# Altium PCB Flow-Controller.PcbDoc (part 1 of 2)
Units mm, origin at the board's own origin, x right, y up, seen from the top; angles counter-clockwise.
Board outline 85 x 90 mm, 2 copper layers (Top Layer, Bottom Layer), stack 1.571 mm thick; 113 components, 85 nets, 341 pads, 150 vias.
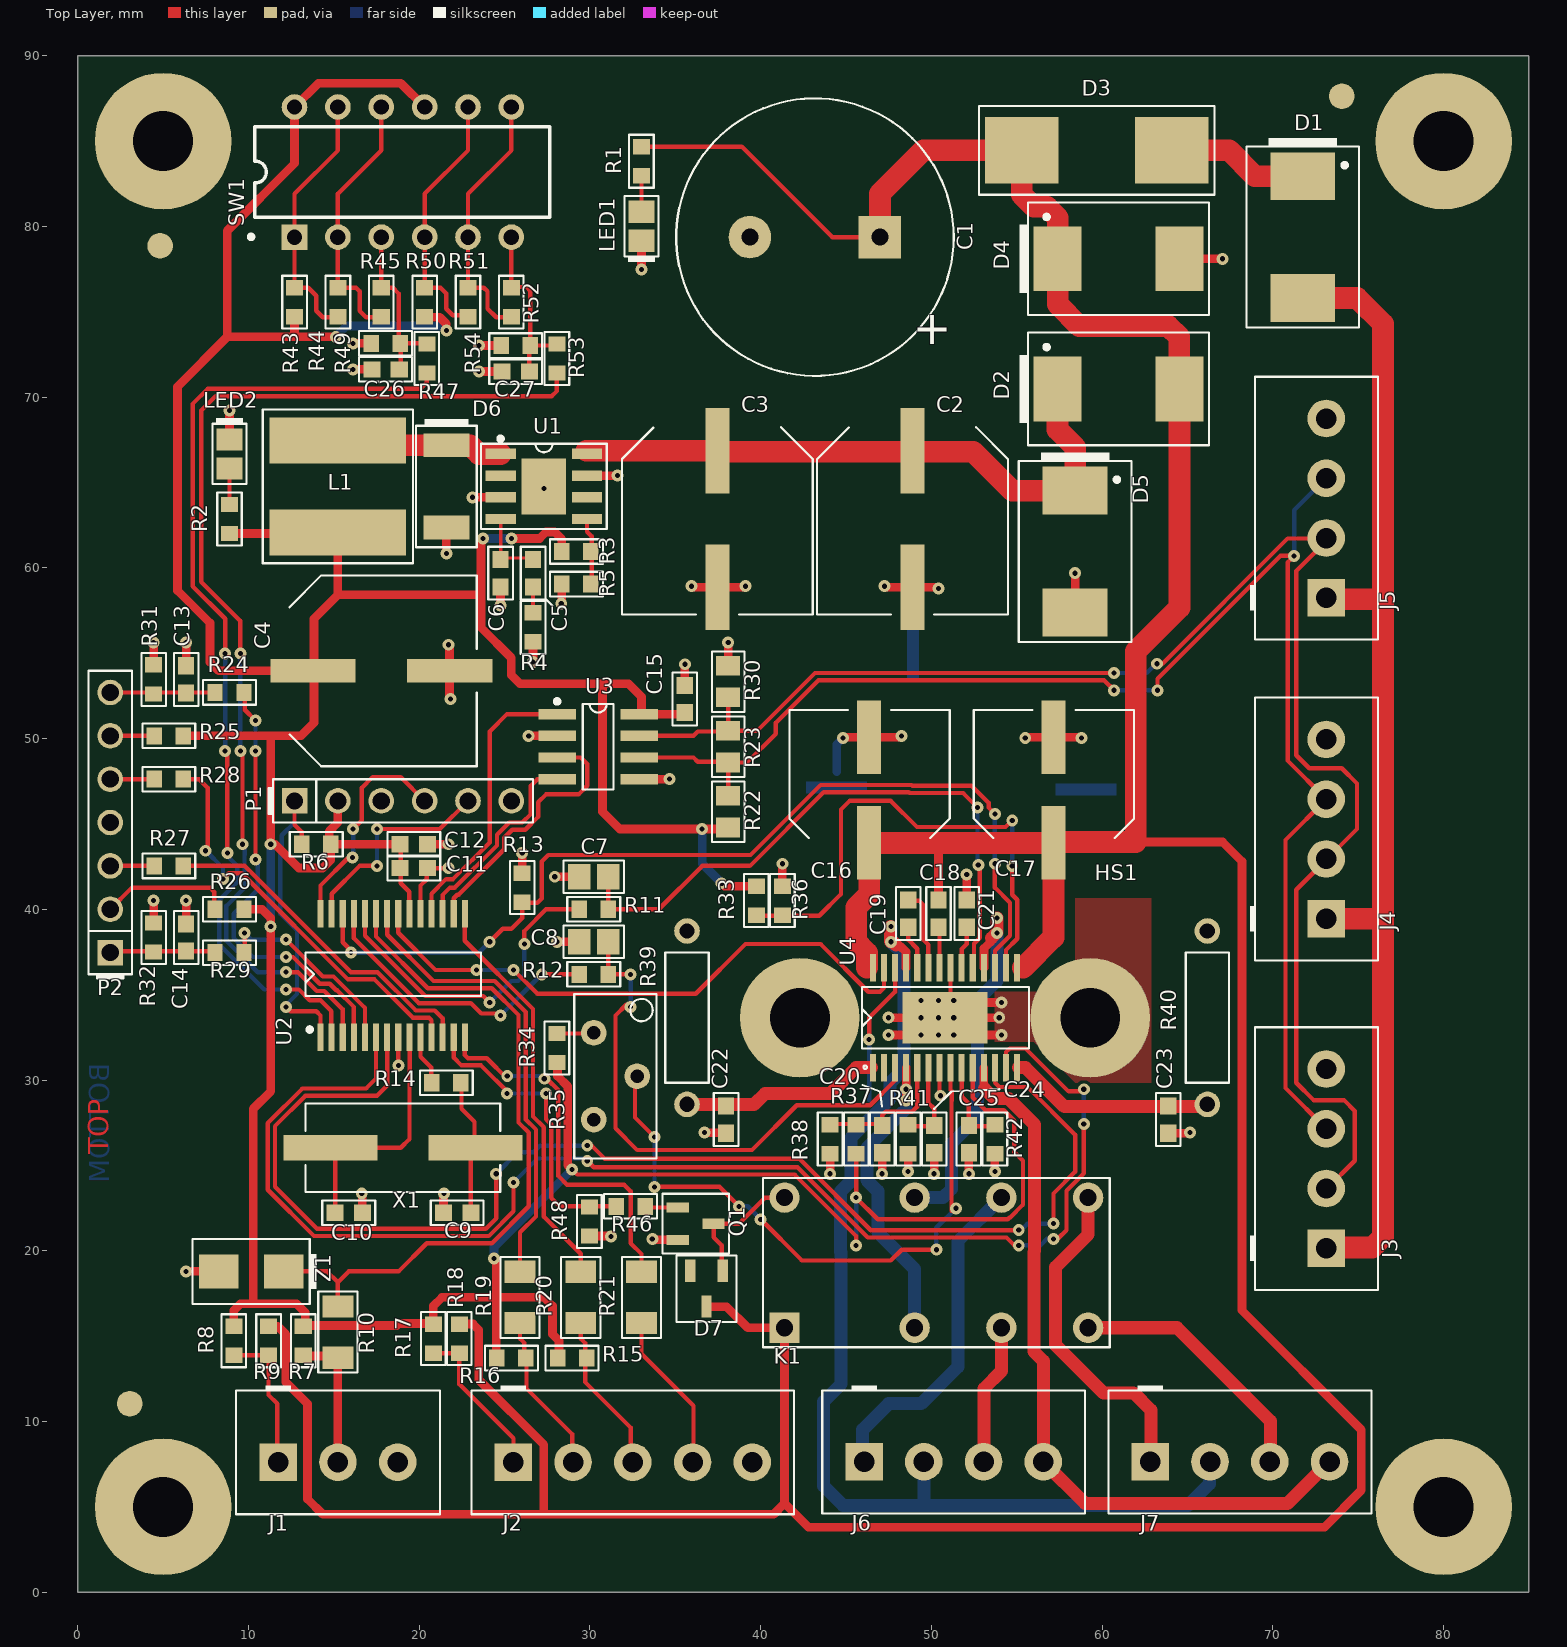
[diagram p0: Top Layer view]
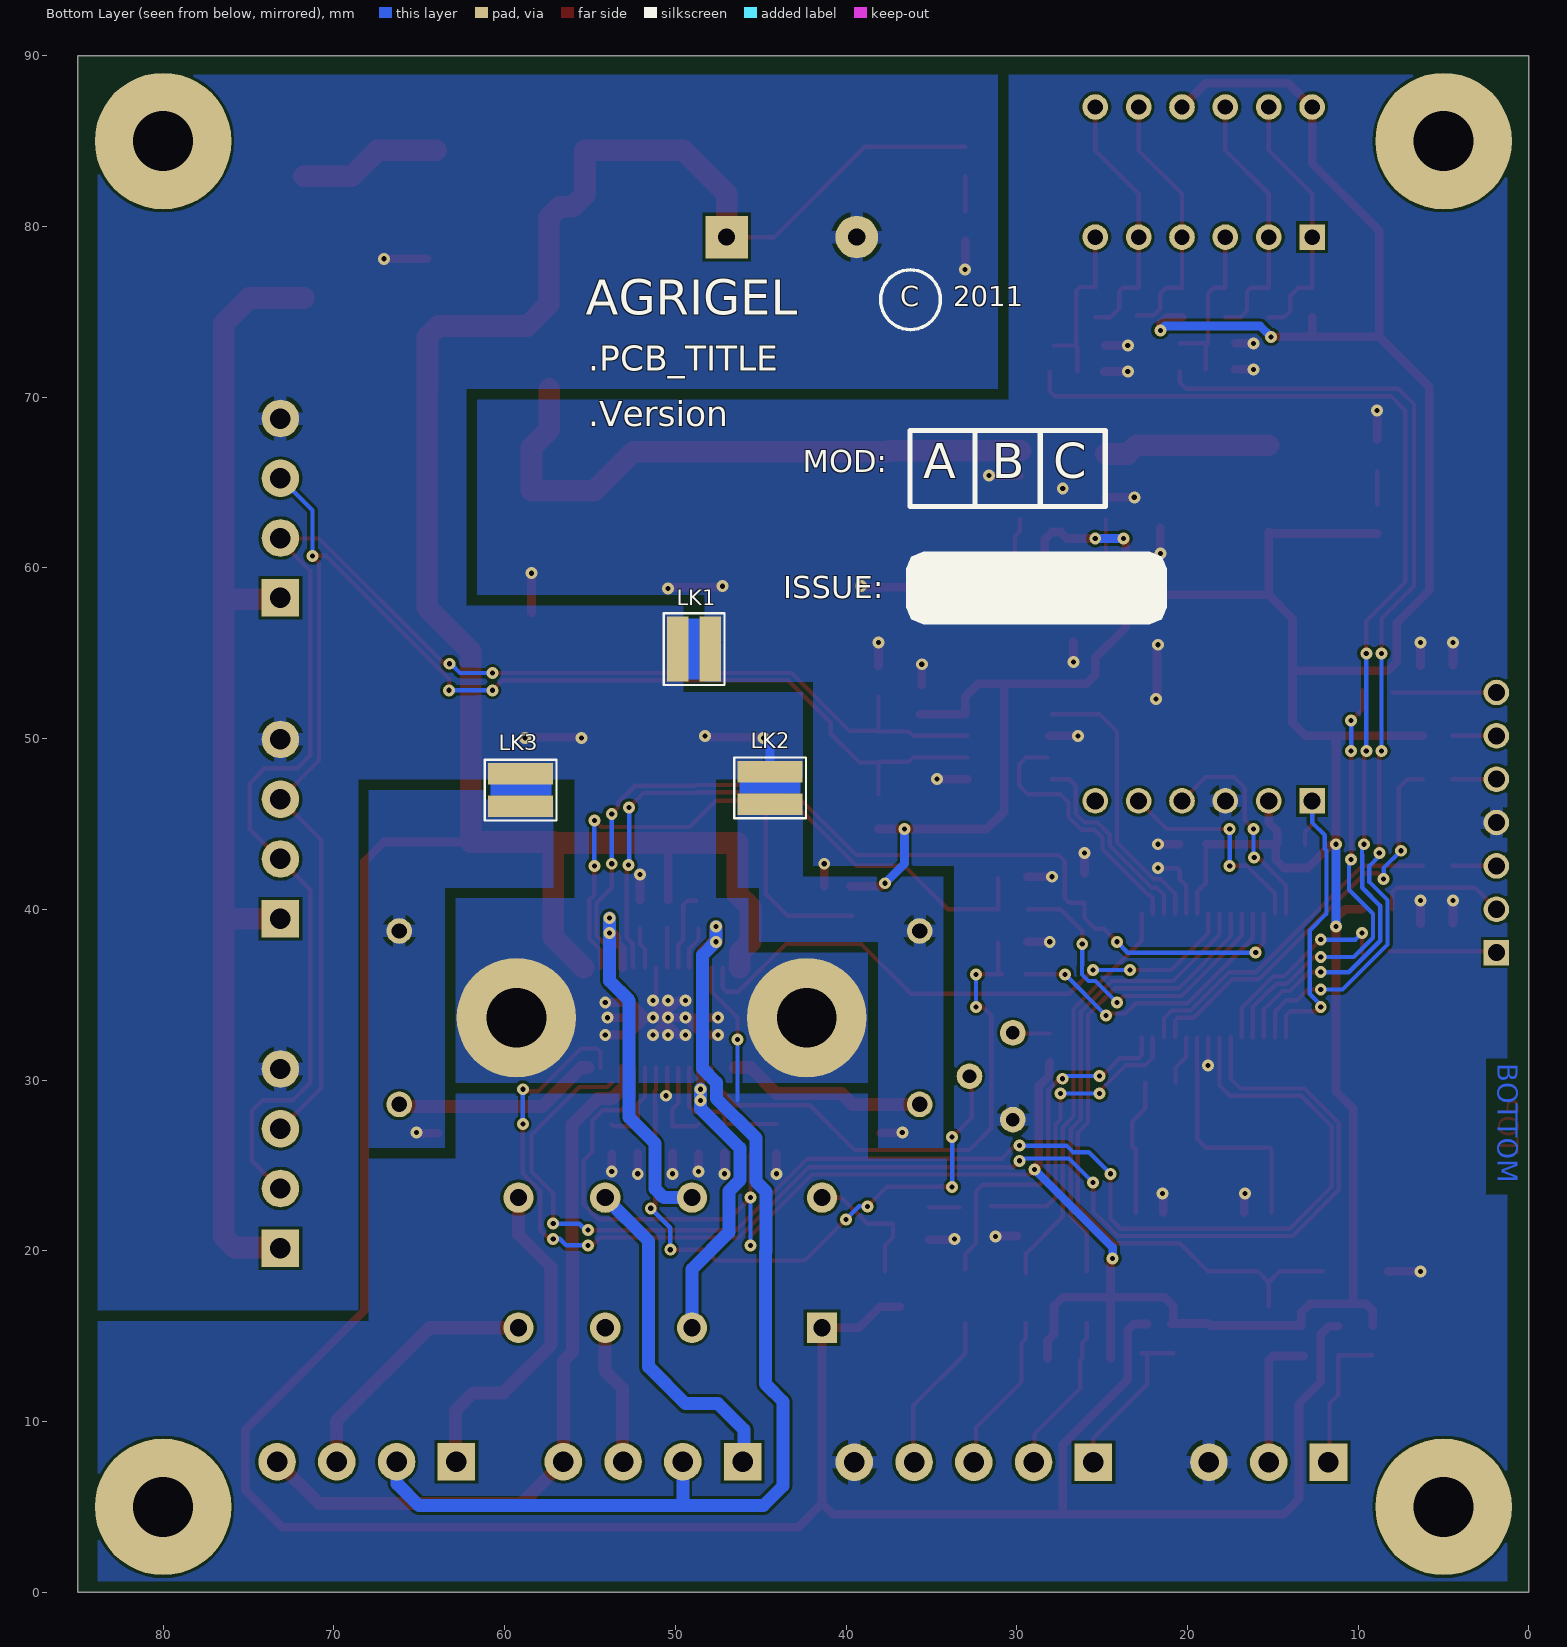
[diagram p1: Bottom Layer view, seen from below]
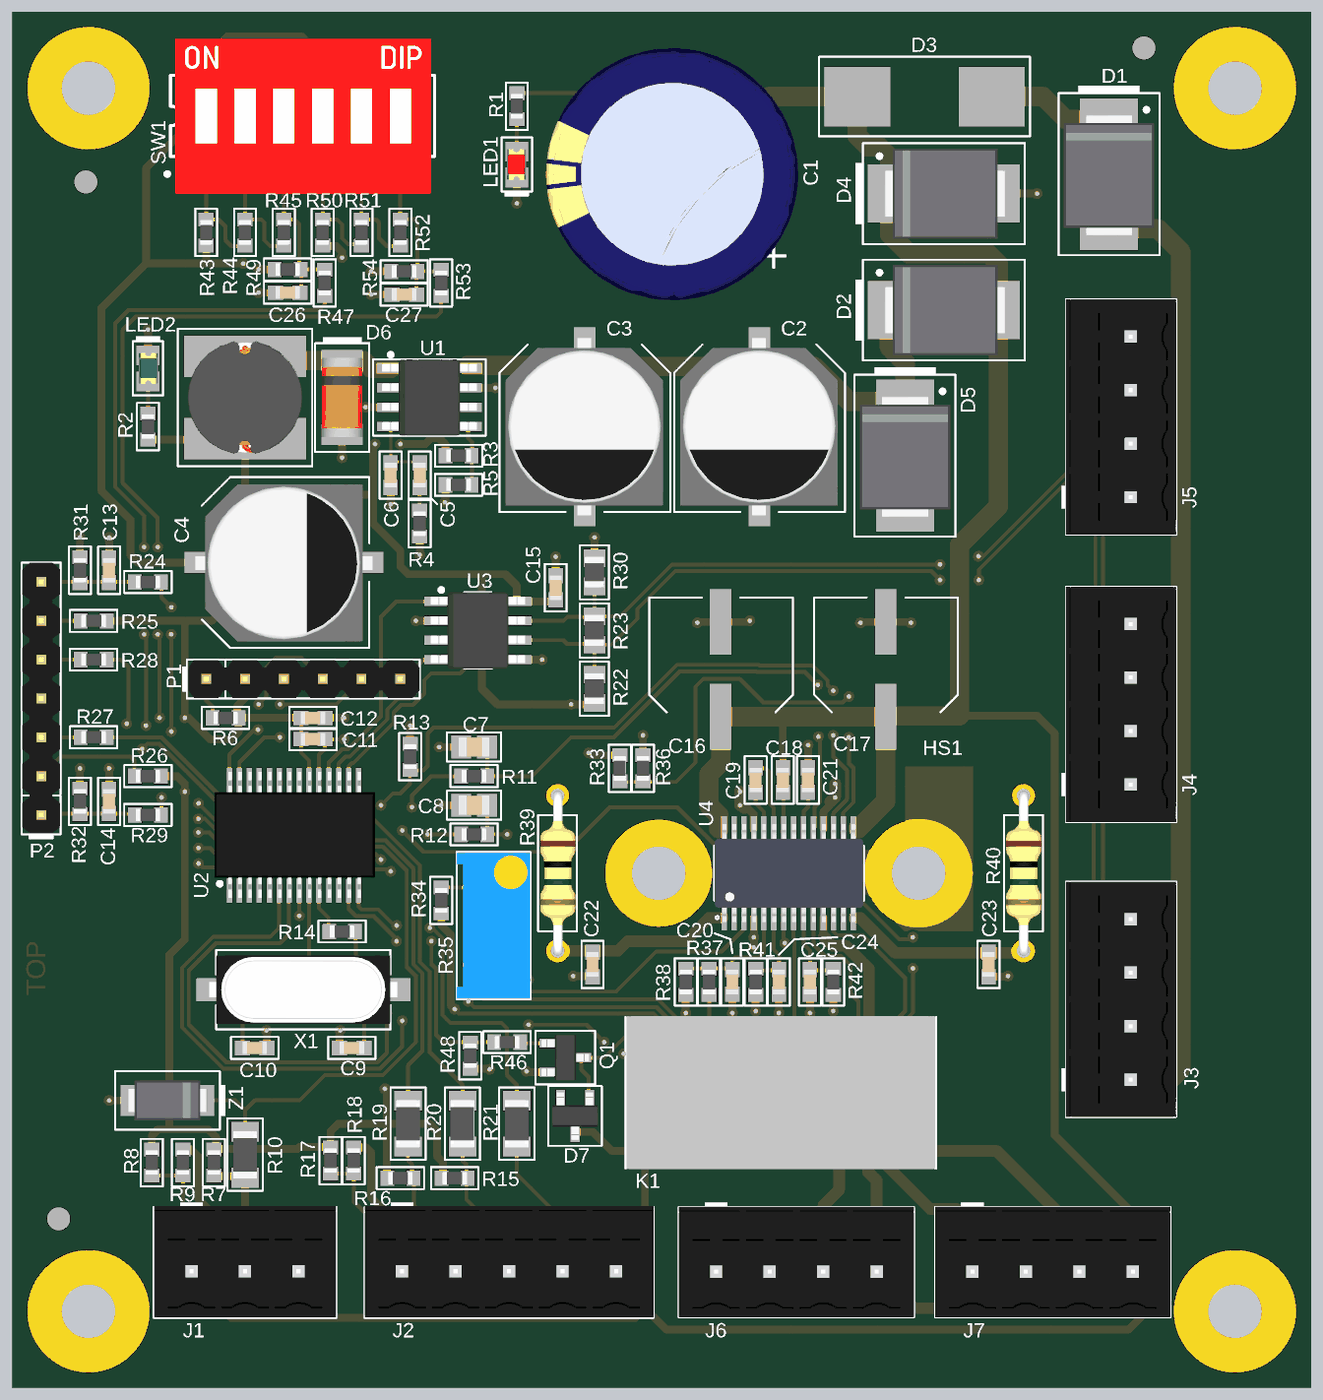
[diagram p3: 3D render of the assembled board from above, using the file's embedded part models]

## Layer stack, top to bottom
Top Layer: signal copper 0.0356
Dielectric: prepreg 1.5, FR-4, Dk 4.2
Bottom Layer: signal copper 0.0356

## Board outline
0,0 85,0 85,90 0,90

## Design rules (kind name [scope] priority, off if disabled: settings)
Clearance [All] p1: gap=0.17
ComponentClearance [All] p1: gap=0 collisioncheckmode=3 verticalgap=0.025 showdistances=FALSE
FabricationTestPointUsage TestPointUsage [All] p1: valid=0 allowmultiple=FALSE
FabricationTestpoint Testpoint [All] p1: side=3 testpointundercomponent=TRUE minsize=1.016 maxsize=2.54 preferedsize=1.524 minholesize=0 maxholesize=1.016 preferedholesize=0.813 testpointgrid=0.025 allowsidetop=TRUE allowsidebottom=TRUE usegrid=TRUE gridtolerance=0
HoleSize [All] p1: absolutevalues=TRUE maxlimit=5 minlimit=0.25 maxpercent=80.000 minpercent=20.000
PlaneClearance [All] p1: clearance=0.5
PolygonConnect PolygonConnect_8 [All vs IsNamedPolygon('Top - GND1-HSK')] p1: connectstyle=Direct reliefconductorwidth=0.254 reliefentries=4 polygonreliefangle="90 Angle" airgapwidth=0.254
PolygonConnect PolygonConnect_7 [All vs IsNamedPolygon('Bot - GND1-HSK')] p2: connectstyle=Direct reliefconductorwidth=0.254 reliefentries=4 polygonreliefangle="90 Angle" airgapwidth=0.254
PolygonConnect PolygonConnect_6 [All vs IsNamedPolygon('Bot - GND4a') Or  IsNamedPolygon('Bot - GND2a') Or  IsNamedPolygon('Bot - GND3a')] p3: connectstyle=Direct reliefconductorwidth=0.254 reliefentries=4 polygonreliefangle="90 Angle" airgapwidth=0.254
PolygonConnect PolygonConnect_5 [All vs IsNamedPolygon('Bot - GND1a')] p4: connectstyle=Direct reliefconductorwidth=0.254 reliefentries=4 polygonreliefangle="90 Angle" airgapwidth=0.254
PolygonConnect PolygonConnectVia [All vs isvia] p5: connectstyle=Direct reliefconductorwidth=0.25 reliefentries=4 polygonreliefangle="90 Angle" airgapwidth=0.254
PolygonConnect PolygonConnect_4 [All vs IsNamedPolygon('Bot - GND2')] p6: connectstyle=Relief reliefconductorwidth=0.762 reliefentries=4 polygonreliefangle="90 Angle" airgapwidth=0.254
PolygonConnect PolygonConnect_3 [All vs IsNamedPolygon('Bot - GND1')] p7: connectstyle=Relief reliefconductorwidth=0.762 reliefentries=4 polygonreliefangle="90 Angle" airgapwidth=0.254
PolygonConnect PolygonConnect_2 [All vs IsNamedPolygon('Bot - GND4')] p8: connectstyle=Relief reliefconductorwidth=0.762 reliefentries=4 polygonreliefangle="90 Angle" airgapwidth=0.254
PolygonConnect PolygonConnect_1 [All vs IsNamedPolygon('Bot - GND3')] p9: connectstyle=Relief reliefconductorwidth=0.762 reliefentries=4 polygonreliefangle="90 Angle" airgapwidth=0.254
PolygonConnect [All] p10: connectstyle=Relief reliefconductorwidth=0.4 reliefentries=4 polygonreliefangle="90 Angle" airgapwidth=0.254
RoutingCorners [All] p1: cornerstyle=45-Degree minsetback=2.5 maxsetback=2.5
RoutingVias [All] p1: holewidth=0.3 width=0.7 viastyle="Through Hole" minholewidth=0.3 minwidth=0.7 maxholewidth=0.3 maxwidth=0.7
ShortCircuit ShortCircuit_LK1 [(InComponent('LK1'))] p1: allowed=TRUE
ShortCircuit ShortCircuit_LK2 [(InComponent('LK2'))] p2: allowed=TRUE
ShortCircuit ShortCircuit_LK3 [(InComponent('LK3'))] p3: allowed=TRUE
ShortCircuit [All] p4: allowed=FALSE
SilkToSolderMaskClearance SilkscreenOverComponentPads [IsPad] p1: minsilkscreentomaskgap=0.254 clearancetoexposedcopper=TRUE
SolderMaskExpansion [All] p1: expansion=0.05
Width "Width_High Power" [InNetClass('High Power')] p1: maxlimit=1.5 minlimit=0.5 preferedwidth=1
Width Width_Power [InNetClass('Power')] p2: maxlimit=1 minlimit=0.3 preferedwidth=0.5
Width [All] p3: maxlimit=2 minlimit=0.2 preferedwidth=0.2
20 further rules are at their usual default settings.

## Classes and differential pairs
component class Flow-Controller-2: C16 C17 C18 C19 C20 C21 C22 C23 C24 C25 C26 C27 D7 HS1 J6 J7 K1 Q1 R33 R34 R35 R36 R37 R38 R39 R40 R41 R42 R43 R44 R45 R46 R47 R48 R49 R50 R51 R52 R53 R54 SW1 U4
component class Flow-Controller-1: C1 C2 C3 C4 C5 C6 C7 C8 C9 C10 C11 C12 C13 C14 C15 D1 D2 D3 D4 D5 D6 J1 J2 J3 J4 J5 L1 LED1 LED2 LK1 LK2 LK3 P1 P2 R1 R2 R3 R4 R5 R6 R7 R8 R9 R10 R11 R12 R13 R14 R15 R16 R17 R18 R19 R20 R21 R22 R23 R24 R25 R26 R27 R28 R29 R30 R31 R32 U1 U2 U3 X1 Z1

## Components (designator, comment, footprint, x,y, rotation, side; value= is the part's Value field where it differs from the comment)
C1 "CAP-EL_2200uF_35V_20%-YXF" EL-RAD-16X31.5 43.18,79.375 r180 top
C2 "100uF35V-20%-EEVFC" CAP-EL-SMD-10x10.5 48.895,62.865 r270 top
C3 "100uF35V-20%-EEVFC" CAP-EL-SMD-10x10.5 37.465,62.865 r270 top
C4 "470uF-35V-20%-LZ" CAP-EL-SMD-10x10.5 17.78,53.975 r0 top
C5 "22nF_C0603_50V_10%_X7R" CAPC0603X85N 26.67,59.69 r270 top
C6 "220pF_C0603_50V_10%_NP0" CAPC0603X85N 24.765,59.69 r270 top
C7 "DNF_C0805_50V_10%_X7R" CAPC0805X110N 30.226,41.91 r180 top
C8 "DNF_C0805_50V_10%_X7R" CAPC0805X110N 30.226,38.1 r180 top
C9 "33pF_C0603_50V_10%_NP0" CAPC0603X85N 22.225,22.225 r180 top
C10 "33pF_C0603_50V_10%_NP0" CAPC0603X85N 15.875,22.225 r0 top
C11 "10nF_C0603_50V_10%_X7R" CAPC0603X85N 19.685,42.418 r0 top
C12 "100nF_C0603_50V_10%_X7R" CAPC0603X85N 19.685,43.815 r0 top
C13 "10nF_C0603_50V_10%_X7R" CAPC0603X85N 6.35,53.467 r90 top
C14 "10nF_C0603_50V_10%_X7R" CAPC0603X85N 6.35,38.354 r90 top
C15 "100nF_C0603_50V_10%_X7R" CAPC0603X85N 35.56,52.324 r90 top
C16 "100uF-50V-20%-LZ" CAP-EL-SMD-8x10.5 46.355,46.99 r90 top
C17 "100uF-50V-20%-LZ" CAP-EL-SMD-8x10.5 57.15,46.99 r90 top
C18 "220nF_C0603_50V_10%_X7R" CAPC0603X85N 50.419,39.751 r270 top
C19 "220nF_C0603_50V_10%_X7R" CAPC0603X85N 48.641,39.751 r90 top
C20 "100nF_C0603_50V_10%_X7R" CAPC0603X85N 47.117,26.543 r270 top
C21 "220nF_C0603_50V_10%_X7R" CAPC0603X85N 52.07,39.751 r90 top
C22 "100nF_C0603_50V_10%_X7R" CAPC0603X85N 37.973,27.686 r270 top
C23 "100nF_C0603_50V_10%_X7R" CAPC0603X85N 63.881,27.686 r270 top
C24 "1.0nF_C0603_50V_10%_X7R" CAPC0603X85N 50.165,26.543 r270 top
C25 "1.0nF_C0603_50V_10%_X7R" CAPC0603X85N 52.197,26.543 r270 top
C26 "100nF_C0603_50V_10%_X7R" CAPC0603X85N 18.034,71.628 r180 top
C27 "100nF_C0603_50V_10%_X7R" CAPC0603X85N 25.654,71.501 r180 top
D1 "ER3M" SMC 71.755,79.375 r270 top
D2 "ER3M" SMC 60.96,70.485 r0 top
D3 "0160 003. MR" LF-0160 59.69,84.455 r180 top
D4 "SMCJ26A" SMC 60.96,78.105 r0 top
D5 "SMCJ26A" SMC 58.42,60.96 r270 top
D6 "SMS2100" DO-213AB 21.59,64.77 r270 top
D7 "BAS16" SOT23 36.83,17.78 r270 top
HS1 "Heatsink-A3979" HEATSINK-A3979 50.8,33.655 r90 top
J1 "MCV 1,5/3-G-3.5" MCV350-3-V 15.24,7.62 r180 top
J2 "MCV 1,5/5-G-3.5" MCV350-5-V 32.512,7.62 r180 top
J3 "MCV 1,5/4-G-3.5" MCV350-4-V 73.152,25.4 r270 top
J4 "MCV 1,5/4-G-3.5" MCV350-4-V 73.152,44.704 r270 top
J5 "MCV 1,5/4-G-3.5" MCV350-4-V 73.152,63.5 r270 top
J6 "MCV 1,5/4-G-3.5" MCV350-4-V 51.308,7.62 r180 top
J7 "MCV 1,5/4-G-3.5" MCV350-4-V 68.072,7.62 r180 top
K1 "V23105-A5003-A201-12V" REL-D2n 50.292,19.304 r90 top
L1 "SDR0805-330K" SDR0805 15.24,64.77 r270 top
LED1 "RED_0805_SMD" LED0805-Red 33.02,80.01 r90 top
LED2 "GREEN_0805_SMD" LED0805-Green 8.89,66.675 r270 top
LK1 "Link-SMD-10A-Closed" SLINK-10A-C 48.895,55.245 r180 bottom
LK2 "Link-SMD-10A-Closed" SLINK-10A-C 44.45,47.117 r270 bottom
LK3 "Link-SMD-10A-Closed" SLINK-10A-C 59.055,46.99 r270 bottom
P1 "SIL6P-2.54" SIL6P-2.54 19.05,46.355 r0 top
P2 "SIL7P-2.54" SIL7P-2.54 1.905,45.085 r90 top
Q1 "BC817" SOT23 36.195,21.59 r0 top
R1 "10K_R0603_1%" RESC0603X60N 33.02,83.82 r270 top
R2 "470R_R0603_1%" RESC0603X60N 8.89,62.865 r90 top
R3 "10K_R0603_1%" RESC0603X60N 29.21,60.96 r0 top
R4 "4K7_R0603_1%" RESC0603X60N 26.67,56.515 r270 top
R5 "3K3_R0603_1%" RESC0603X60N 29.21,59.055 r180 top
R6 "10K_R0603_1%" RESC0603X60N 13.97,43.815 r180 top
R7 "10K_R0603_1%" RESC0603X60N 13.208,14.732 r270 top
R8 "0R_R0603_1%" RESC0603X60N 9.144,14.732 r270 top
R9 "DNP_R0603_1%" RESC0603X60N 11.176,14.732 r270 top
R10 "100R_R1206_1%" RESC1206X71N 15.24,15.24 r270 top
R11 "1K_R0603_1%" RESC0603X60N 30.226,40.005 r0 top
R12 "1K_R0603_1%" RESC0603X60N 30.226,36.195 r0 top
R13 "2K2_R0603_1%" RESC0603X60N 26.035,41.275 r90 top
R14 "0R_R0603_1%" RESC0603X60N 21.59,29.845 r180 top
R15 "1K_R0603_1%" RESC0603X60N 28.956,13.716 r0 top
R16 "10K_R0603_1%" RESC0603X60N 25.4,13.716 r0 top
R17 "0R_R0603_1%" RESC0603X60N 20.828,14.859 r270 top
R18 "DNP_R0603_1%" RESC0603X60N 22.352,14.859 r270 top
R19 "100R_R1206_1%" RESC1206X71N 25.908,17.272 r270 top
R20 "100R_R1206_1%" RESC1206X71N 29.464,17.272 r270 top
R21 "100R_R1206_1%" RESC1206X71N 33.02,17.272 r270 top
R22 "DNP_R0805_1%" RESC0805X65N 38.1,45.72 r90 top
R23 "DNP_R0805_1%" RESC0805X65N 38.1,49.53 r90 top
R24 "1K_R0603_1%" RESC0603X60N 8.89,52.705 r180 top
R25 "1K8_R0603_1%" RESC0603X60N 5.334,50.165 r180 top
R26 "1K_R0603_1%" RESC0603X60N 8.89,40.005 r180 top
R27 "470R_R0603_1%" RESC0603X60N 5.334,42.545 r180 top
R28 "470R_R0603_1%" RESC0603X60N 5.334,47.625 r180 top
R29 "1K_R0603_1%" RESC0603X60N 8.89,37.465 r180 top
R30 "DNP_R0805_1%" RESC0805X65N 38.1,53.34 r90 top
R31 "1K_R0603_1%" RESC0603X60N 4.445,53.467 r90 top
R32 "1K_R0603_1%" RESC0603X60N 4.445,38.354 r90 top
R33 "DNP_R0603_1%" RESC0603X60N 39.751,40.513 r270 top
R34 "2K2_R0603_1%" RESC0603X60N 28.067,31.877 r90 top
R35 "3296Y-1-103" 3296Y-THP 31.496,30.226 r270 top
R36 "1K_R0603_1%" RESC0603X60N 41.275,40.513 r90 top
R37 "4K7_R0603_1%" RESC0603X60N 45.593,26.543 r90 top
R38 "4K7_R0603_1%" RESC0603X60N 44.069,26.543 r270 top
R39 "0R27-0.250W-5%" RES-0.250W 35.687,33.655 r270 top
R40 "0R27-0.250W-5%" RES-0.250W 66.167,33.655 r270 top
R41 "33K_R0603_1%" RESC0603X60N 48.641,26.543 r270 top
R42 "33K_R0603_1%" RESC0603X60N 53.721,26.543 r270 top
R43 "3K9_R0603_1%" RESC0603X60N 12.7,75.565 r90 top
R44 "2K2_R0603_1%" RESC0603X60N 15.24,75.565 r90 top
R45 "1K_R0603_1%" RESC0603X60N 17.78,75.565 r90 top
R46 "2K2_R0603_1%" RESC0603X60N 32.385,22.606 r0 top
R47 "1K_R0603_1%" RESC0603X60N 20.447,72.263 r90 top
R48 "10K_R0603_1%" RESC0603X60N 29.972,21.717 r270 top
R49 "5K6_R0603_1%" RESC0603X60N 18.034,73.152 r180 top
R50 "3K9_R0603_1%" RESC0603X60N 20.32,75.565 r90 top
R51 "2K2_R0603_1%" RESC0603X60N 22.86,75.565 r90 top
R52 "1K_R0603_1%" RESC0603X60N 25.4,75.565 r90 top
R53 "1K_R0603_1%" RESC0603X60N 28.067,72.263 r90 top
R54 "5K6_R0603_1%" RESC0603X60N 25.654,73.025 r180 top
SW1 "DS-06" DIP-SW6 19.05,83.185 r90 top
U1 "L5973D-HSOP8" HSOP8 27.305,64.77 r0 top
U2 "PIC18F25K22-I/SS" SSOP28 18.415,36.195 r90 top
U3 "DS75176BM" SO8 30.48,49.53 r0 top
U4 "A3979SLPTR" TSSOP28-4.4-LP 50.8,33.655 r90 top
X1 "XTAL_11.0592MHz_STCX15" XT-HEX15 19.05,26.035 r180 top
Z1 "1SMA5918BT3" SMA 10.16,18.796 r180 top

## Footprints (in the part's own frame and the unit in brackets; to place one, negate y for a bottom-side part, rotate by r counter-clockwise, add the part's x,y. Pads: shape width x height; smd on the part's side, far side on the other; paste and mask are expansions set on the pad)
3296Y-THP [mm] "Variable Resistor, Bourns, Straight THP"
  round 1.5 hole 0.8 paste+0 mask+0.05: 1(-2.54,-1.27) 2(0,1.27) 3(2.54,-1.27)
  silkscreen extent -4.83,-2.41 4.83,2.41, body extent -4.76,-2.43 4.77,2.4, height 11.55
CAP-EL-SMD-8x10.5 [mm] "CAP El SMD 8.0x10.5mm"
  rect 4.3x1.4 smd mask+0.025: 1(-3.1,0) 2(3.1,0)
  silkscreen extent -2.81,-4.73 4.68,4.67, body extent -4.18,-4.2 4.18,4.15, height 10.5
CAP-EL-SMD-10x10.5 [mm] "CAP El SMD 10.0x10.0mm"
  rect 5x1.4 smd mask+0.025: 1(-4,0) 2(4,0)
  silkscreen extent -5.37,-5.59 5.59,5.59, body extent -5.8,-5.17 5.8,5.13, height 10.21
CAPC0603X85N [mm] "Chip Capacitor, 0603, 2-Leads, Body 1.6x0.8mm, IPC Medium Density"
  rect 1x0.95 smd paste+0 mask+0.05: 1(-0.8,0) 2(0.8,0)
  silkscreen extent -1.55,-0.72 1.55,0.72, body extent -0.8,-0.4 0.8,0.4, height 0.8
CAPC0805X110N [mm] "Chip Capacitor, 0805, 2-Leads, Body 2.0x1.3mm, IPC Medium Density"
  rect 1.3x1.5 smd paste+0 mask+0.05: 1(-0.85,0) 2(0.85,0)
  silkscreen extent -1.77,-0.95 1.77,0.95, body extent -1,-0.63 1,0.63, height 1.22
DIP-SW6 [mm] "DIP Switch 6 Way"
  rect 1.5x1.5 hole 0.9: 1(-3.81,6.35)
  round 1.5 hole 0.9: 2(-3.81,3.81) 3(-3.81,1.27) 4(-3.81,-1.27) 5(-3.81,-3.81) 6(-3.81,-6.35) 7(3.81,-6.35) 8(3.81,-3.81) 9(3.81,-1.27) 10(3.81,1.27) 11(3.81,3.81) 12(3.81,6.35)
  silkscreen extent -3.92,-8.59 2.67,9.02, body extent -5.08,-8.38 5.08,8.38, height 6.9
DO-213AB [mil] "DO-213AB 5.0x2.5mm"
  rect 55x106 smd mask+1: 1(-95,0) 2(95,0)
  silkscreen extent -155,-70 140,70, body extent -102,-53 102,53, height 106
EL-RAD-16X31.5 [mil] "Capacitor, Electrolytic, THP, Radial, Dia 16mm, Pitch 7.5mm"
  rect 98x98 hole 39.37: 1(-150,0)
  round 98 hole 39.37: 2(150,0)
  silkscreen extent -320,-320 320,320, body extent -325,-325 325,325, height 1266
HEATSINK-A3979 [mm] "HEATSINK A3979 25.0X15.0mm"
  round 7 hole 3.5: 1(0,8.5) 2(0,-8.5)
  body extent -7.5,-11.5 7.5,11.5, height 13.2
HSOP8 [mil] "HSOP 8-Leads, Body 5.0x4.0mm, Pitch 1.27mm"
  rect 70x24 smd paste+0 mask+1.97: 1(-99.49,75) 2(-99.49,25) 3(-99.49,-25) 4(-99.49,-75) 5(99.49,-75) 6(99.49,-25) 7(99.49,25) 8(99.49,75)
  rect 102.36x129.92 smd mask+1: 9(0,0)
  silkscreen extent -145,-98 145,115, body extent -122,-98 122,98, height 70
LED0805-Green [mm] "LED, 0805, 2-Leads, Body 2.0x1.3mm, IPC Medium Density"
  rect 1.3x1.5 smd paste+0 mask+0.025: 1(-0.85,0) 2(0.85,0)
  silkscreen extent -2.1,-1 1.77,0.99, body extent -1.01,-0.6 1.01,0.65, height 1.2
LED0805-Red [mm] "LED, 0805, 2-Leads, Body 2.0x1.3mm, IPC Medium Density"
  rect 1.3x1.5 smd paste+0 mask+0.025: 1(-0.85,0) 2(0.85,0)
  silkscreen extent -2.1,-1 1.77,0.99, body extent -1.01,-0.6 1.01,0.65, height 1.2
LF-0160 [mm] "Fuse 0160 10.9x4.8mm"
  rect 4.3x3.9 smd mask+0.025: 1(-4.4,0) 2(4.4,0)
  silkscreen extent -6.9,-2.6 6.9,2.6, body extent -5.5,-2.4 5.5,2.4, height 4.8
MCV350-3-V [mm] "MCV 3 way 3.5mm 11.9x7.25mm"
  rect 2.2x2.2 hole 1.2: 1(3.5,0)
  round 2.2 hole 1.2: 2(0,0) 3(-3.5,0)
  silkscreen extent -5.97,-4.5 5.97,3.05, body extent -5.95,-4.25 5.95,3, height 9.2
MCV350-4-V [mm] "MCV 4 way 3.5mm 15.4x7.25mm"
  rect 2.2x2.2 hole 1.2: 1(5.25,-0.025)
  round 2.2 hole 1.2: 2(1.75,-0.025) 3(-1.75,-0.025) 4(-5.25,-0.025)
  silkscreen extent -7.7,-4.5 7.7,3, body extent -7.7,-4.23 7.7,3.03, height 9.2
MCV350-5-V [mm] "MCV 5 way 3.5mm 18.9x7.25mm"
  rect 2.2x2.2 hole 1.2: 1(7,0)
  round 2.2 hole 1.2: 2(3.5,0) 3(0,0) 4(-3.5,0) 5(-7,0)
  silkscreen extent -9.45,-4.5 9.45,3.05, body extent -9.45,-4.25 9.45,3, height 9.2
REL-D2n [mil] "D2n 10.0x20.0mm"
  rect 70x70 hole 39.37: 1(-150,350)
  round 70 hole 39.37: 4(-150,50) 6(-150,-150) 8(-150,-350) 9(150,-350) 11(150,-150) 13(150,50) 16(150,350)
  silkscreen extent -195,-400 195,400, body extent -197,-398 197,398, height 440
RES-0.250W [mil] "Res 0.25W 7.6x2.3mm"
  round 59 hole 35.43: 1(-200,0) 2(200,0)
  silkscreen extent -150,-50 150,50, body extent -212,-45 212,46, height 96
RESC0603X60N [mm] "Chip Resistor, 0603, 2-Leads, Body 1.6x0.8mm, IPC Medium Density"
  rect 0.9x1 smd paste+0 mask+0.05: 1(-0.85,0) 2(0.85,0)
  silkscreen extent -1.55,-0.72 1.55,0.72, body extent -0.8,-0.4 0.8,0.4, height 0.37
RESC0805X65N [mm] "Chip Resistor, 0805, 2-Leads, Body 2.0x1.3mm, IPC Medium Density"
  rect 1.15x1.4 smd paste+0 mask+0.05: 1(-0.925,0) 2(0.925,0)
  silkscreen extent -1.77,-0.95 1.77,0.95, body extent -0.99,-0.62 1.01,0.63, height 0.47
RESC1206X71N [mm] "Chip Resistor, 1206, 2-Leads, Body 3.2x1.6mm, IPC Medium Density"
  rect 1.3x1.8 smd paste+0 mask+0.05: 1(-1.5,0) 2(1.5,0)
  silkscreen extent -2.37,-1.15 2.37,1.15, body extent -1.55,-0.78 1.55,0.77, height 0.47
SDR0805 [mm] "SDR0805 7.8x7.8mm"
  rect 2.7x8 smd mask+0.025: 1(-2.7,0) 2(2.7,0)
  silkscreen extent -4.5,-4.4 4.5,4.4, body extent -3.68,-3.75 3.68,3.75, height 5.05
SIL6P-2.54 [mil] "SIL Strip 2.54mm"
  rect 59x59 hole 39.37: 1(-250,0)
  round 59 hole 39.37: 2(-150,0) 3(-50,0) 4(50,0) 5(150,0) 6(250,0)
  silkscreen extent -310,-50 300,50, body extent -296,-49 300,49, height 323
SIL7P-2.54 [mil] "SIL Strip 2.54mm"
  rect 59x59 hole 39.37: 1(-300,0)
  round 59 hole 39.37: 2(-200,0) 3(-100,0) 4(0,0) 5(100,0) 6(200,0) 7(300,0)
  silkscreen extent -360,-50 350,50, body extent -346,-49 350,49, height 323
SLINK-10A-C [mm] "Solder Link 10Amp Closed"
  rect 1.27x3.8 smd mask+0.025: 1(-0.953,0) 2(0.953,0)
  Top Layer region: -0.381,1.795 0.319,1.795 0.319,-1.778 -0.381,-1.778
  silkscreen extent -1.78,-2.1 1.78,2.1
SMA [mil] "SMA 5.6x2.95mm"
  rect 91x79 smd mask+0.98: 1(-75,0.08) 2(75,0.08)
  silkscreen extent -150,-75 135,75, body extent -102,-51 102,51, height 91
SMC [mm] "Molded Diode, 2-Leads, Body 6.9x5.8mm, IPC Medium Density"
  rect 2.8x3.8 smd mask+0.025: 1(-3.57,0) 2(3.57,0)
  silkscreen extent -5.8,-3.3 5.3,3.3, body extent -3.9,-2.95 4.05,2.95, height 2.3
SO8 [mm] "SOIC, 8-Leads, Body 5.0x4.0mm (max), Pitch 1.27mm, IPC Medium Density"
  rect 2.2x0.6 smd paste+0 mask+0.05: 1(-2.4,1.905) 2(-2.4,0.635) 3(-2.4,-0.635) 4(-2.4,-1.905) 5(2.4,-1.905) 6(2.4,-0.635) 7(2.4,0.635) 8(2.4,1.905)
  silkscreen extent -2.52,-2.5 0.9,2.77, body extent -3.1,-2.5 3.1,2.5, height 1.78
SOT23 [mm] "SOT23, 3-Leads, Body 3.0x2.6mm (max), Pitch 0.95mm, IPC Medium Density"
  rect 1.3x0.6 smd paste+0 mask+0.05: 1(-1.05,0.95) 2(-1.05,-0.95) 3(1.05,0)
  silkscreen extent -1.95,-1.75 1.95,1.75, body extent -1.56,-1.5 1.58,1.5, height 1
SSOP28 [mil] "SSOP 28 0.65mm 5.3x10.2mm"
  rect 63x14 smd mask+1: 1(-145,165) 2(-145,139.41) 3(-145,113.82) 4(-145,88.23) 5(-145,62.64) 6(-145,37.05) 7(-145,11.46) 8(-145,-14.13) 9(-145,-39.72) 10(-145,-65.31) 11(-145,-90.9) 12(-145,-116.49) 13(-145,-142.08) 14(-145,-167.67) 15(140,-167.67) 16(140,-142.08) 17(140,-116.49) 18(140,-90.9) 19(140,-65.31) 20(140,-39.72) 21(140,-14.13) 22(140,11.46) 23(140,37.05) 24(140,62.64) 25(140,88.23) 26(140,113.82) 27(140,139.41) 28(140,165)
  silkscreen extent -132,-205 50,200, body extent -163,-210 160,204, height 76
TSSOP28-4.4-LP [mil] "TSSOP28 LP 4.4x9.7mm"
  rect 63x14 smd mask+0.98: 1(-115.16,166.34) 2(-115.16,140.75) 3(-115.16,115.16) 4(-115.16,89.57) 5(-115.16,63.98) 6(-115.16,38.39) 7(-115.16,12.8) 8(-115.16,-12.79) 9(-115.16,-38.38) 10(-115.16,-63.97) 11(-115.16,-89.56) 12(-115.16,-115.15) 13(-115.16,-140.74) 14(-115.16,-166.33) 15(114.84,-166.33) 16(114.84,-140.74) 17(114.84,-115.15) 18(114.84,-89.56) 19(114.84,-63.97) 20(114.84,-38.38) 21(114.84,-12.79) 22(114.84,12.8) 23(114.84,38.39) 24(114.84,63.98) 25(114.84,89.57) 26(114.84,115.16) 27(114.84,140.75) 28(114.84,166.34)
  rect 118.11x196.85 smd mask+1: 29(0,0)
  silkscreen extent -118,-194 71,191, body extent -126,-192 126,190, height 38
XT-HEX15 [mm] "XTAL-HEX15, 2-Leads, Body 11.1x4.83mm (max), Pitch 4.3mm"
  rect 5.5x1.5 smd paste+0 mask+0.025: 1(-4.25,0) 2(4.25,0)
  silkscreen extent -5.7,-2.6 5.7,2.6, body extent -6.15,-2.25 6.15,2.25, height 5.18

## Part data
C1: library part 2200uF_35V_20%_V-YXF, "Cap Electrolytic THP Radial - Low Imp"
C2 C3: library part 100uF-35V-20%-EEVFC_V, "Cap Electrolytic SMD Low Imp"
C4: library part 470uF-35V-20%-LZ_V, "Cap Electrolytic SMD Low Imp"
C5: library part 22nF_0603N_50V_10%_X7R_V, "Cap Ceramic X7R"
C6: library part 220pF_0603N_50V_10%_NP0_V, "Cap Ceramic NP0"
C7 C8: library part DNF_0805N_50V_10%_X7R_V, "Do not Fit - Cap Ceramic X7R"
C9 C10: library part 33pF_0603N_50V_10%_NP0_V, "Cap Ceramic NP0"
C11 C13 C14: library part 10nF_0603N_50V_10%_X7R_V, "Cap Ceramic X7R"
C12 C15 C20 C22 C23 C26 C27: library part 100nF_0603N_50V_10%_X7R_V, "Cap Ceramic X7R"
C16 C17: library part 100uF-50V-20%-LZ_V, "Cap Electrolytic SMD Low Imp"
C18 C21: library part 220nF_0603N_50V_10%_X7R_V, "Cap Ceramic X7R"
C19: library part 220nF_0603N_50V_10%_X7R_H, "Cap Ceramic X7R"
C24 C25: library part 1nF_0603N_50V_10%_X7R_V, "Cap Ceramic X7R"
D1 D2: library part ER3M_SMC_H, "Diode Rectifier (1000V 3A)"
D3: library part FUSE_0160_003.MR_3AMP, "Fuseblock with Slow-Blo Fuse"
D4 D5: library part SMCJ26A_V, "TVS 1500W SMC"
D6: library part SMS2100_V, "Diode Schottky Rectifier 2Amp 100V"
D7: library part BAS16_SOT23-3N_V, "Diode Small Signal"
HS1: "Heatsink Vertical PCB Mount A3979"
J1 J2 J3 J4 J5 J6 J7: "Header Pluggable 3.5mm Vertical"
K1: "Relay DPDT 12V 3A"
L1: library part 33uH_SDR0805_H, "Inductor Power"
LED1: library part RED_0805_SMD_V, "LED SMD 0805 Red"
LED2: library part GREEN_0805_SMD_V, "LED SMD 0805 Green"
LK1 LK2 LK3: "Link SMD Closed 10Amp"
P1 P2: "Header SIL Male THP, 2.54mm Pitch"
Q1: library part BC817_SOT23, "Transistor NPN General Purpose"
R1 R3 R6 R7 R16 R48: library part 10K_0603_V, "Resistor Chip SMD"
R2 R27 R28: library part 470R_0603_V, "Resistor Chip SMD"
R4 R37 R38: library part 4K7_0603_V, "Resistor Chip SMD"
R5: library part 3K3_0603_V, "Resistor Chip SMD"
R8 R17: library part 0R_0603_V, "Resistor Chip SMD"
R9 R18 R33: library part DNP_0603_V, "Resistor Chip SMD"
R10 R19 R20 R21: library part 100R_1206_H, "Resistor Chip SMD"
R11 R12 R24 R29 R47 R53: library part 1K_0603_H, "Resistor Chip SMD"
R13 R34 R44 R51: library part 2K2_0603_V, "Resistor Chip SMD"
R14: library part 0R_0603_H, "Resistor Chip SMD"
R15 R26 R31 R32 R36 R45 R52: library part 1K_0603_V, "Resistor Chip SMD"
R22 R23 R30: library part DNP_0805_V, "Resistor Chip SMD"
R25: library part 1K8_0603_V, "Resistor Chip SMD"
R35: library part 10K_3296Y-1-103_THP_V, "Variable Resistor THP"
R39 R40: library part 0R27-0.250W-5%_V, "Resistor Metal Film"
R41 R42: library part 33K_0603_V, "Resistor Chip SMD"
R43 R50: library part 3K9_0603_V, "Resistor Chip SMD"
R46: library part 2K2_0603_H, "Resistor Chip SMD"
R49 R54: library part 5K6_0603_V, "Resistor Chip SMD"
SW1: library part SW-DIP-DS-06, "DIP Slide Switch"
U1: "IC Switching Regulator 2.5A"
U2: library part PIC18F25K22-I/SS_SSOP28, "IC Microcontroller 8-Bit"
U3: library part DS75176BM_SO8, "IC 3.3V RS-485 Drivers and Receivers"
U4: library part A3979SLPTR_TSSOP28, "IC Microstepping DMOS Driver"
X1: "Crystal - HEX15"
Z1: library part 1SMA5918BT3_X, "Zener Diode 1.5W"

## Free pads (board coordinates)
  round 8 hole 3.5: 0(5,85) 1(80,85) 2(5,5) 3(80,5)
  round 1.5 smd paste+0 mask+0.05: 1(3.048,11.049) 1(4.826,78.867) 1(74.041,87.63)

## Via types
v1: diameter 0.7, hole 0.3, Top Layer to Bottom Layer, tented both sides, 150 vias

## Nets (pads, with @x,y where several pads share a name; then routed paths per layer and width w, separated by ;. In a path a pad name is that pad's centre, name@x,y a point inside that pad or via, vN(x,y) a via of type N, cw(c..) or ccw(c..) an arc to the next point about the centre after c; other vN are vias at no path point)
485+: J3.3 J4.3 J5.3 R22.2 R23.1 U3.6 | length 88.5
  Top Layer w0.254: U3.6@32.88,48.895 36.068,48.895 36.322,48.641 R23.1@37.973,48.641 ; R22.2@38.1,46.736 R23.1@38.1,48.605 39.207,48.605 40.894,50.292 40.894,50.927 43.391,53.424 60.114,53.424 v1(60.706,52.832) ; v1(63.246,52.832) 63.246,53.502 70.45,60.706 v1(71.247,60.706) 70.866,60.325 70.866,48.715 J4.3@73.127,46.454 70.739,44.066 70.739,29.538 J3.3@73.127,27.15
  Bottom Layer w0.254: v1(60.706,52.832) v1(63.246,52.832) ; v1(71.247,60.706) 71.247,63.373 J5.3@73.152,65.278
485-: J3.2 J4.2 J5.2 R23.2 R30.1 U3.7 | length 93
  Top Layer w0.254: U3.7@32.88,50.165 36.068,50.165 36.322,50.419 R23.2@38.1,50.419 ; R30.1@38.1,52.451 R30.1@38.1,52.415 R23.2@38.1,50.455 39.787,50.455 43.18,53.848 v1(60.706,53.848) ; v1(63.215,54.387) 63.531,54.387 70.866,61.722 J5.2@73.025,61.722 ; J5.2@73.127,61.75 73.127,61.57 71.374,59.817 71.374,49.022 72.136,48.26 74.041,48.26 74.93,47.371 74.93,44.704 71.374,41.148 71.374,29.845 72.39,28.829 74.168,28.829 74.803,28.194 74.803,25.273 J3.2@73.152,23.622
  Bottom Layer w0.254: v1(60.706,53.848) 62.611,53.848 63.15,54.387 v1(63.215,54.387)
+5V: C4.1 C11.1 C12.1 C15.1 L1.2 P1.2 R2.1 R3.1 R6.1 R7.1 R8.1 R15.1 R16.1 R17.1 R22.1 R25.1 R26.1 R33.1 R34.1 R37.1 R43.1 R50.1 SW1.9 SW1.12 U2.20 U3.8 U4.10 | length 290.9
  Top Layer w0.254: C12.1@18.923,43.688 18.923,41.529 19.424,41.028 U2.20@19.424,39.751 ; v1(28.956,24.765) 29.253,24.468 41.988,24.468 45.593,20.863 v1(45.593,20.32) ; R37.1@45.593,25.654 v1(45.593,23.114) 46.863,21.844 54.483,21.844 54.567,21.928 54.593,21.928 55.372,22.707 55.372,25.273 54.864,25.781 54.864,27.62 54.249,28.235 53.172,28.235 52.425,28.982 U4.10@52.425,30.73
  Top Layer w0.508: R25.1@6.184,50.165 11.303,50.165 ; R2.1@8.89,62.015 L1.2@14.947,62.015 ; R8.1@9.144,15.621 9.144,16.51 9.525,16.891 10.287,16.891 ; R26.1@9.779,40.005 10.795,40.005 11.303,39.497 v1(11.303,38.989) 11.303,29.337 10.287,28.321 10.287,16.891 ; R43.1@12.7,74.676 12.7,73.533 ; C4.1@13.843,53.975 13.843,50.927 13.081,50.165 11.303,50.165 ; v1(15.113,73.533) 12.7,73.533 ; P1.2@15.24,46.355 15.24,45.085 14.732,44.577 14.732,43.815 R6.1@14.82,43.815 ; L1.2@15.24,62.103 L1.2@15.24,62.07 15.24,58.42 ; C12.1@18.885,43.815 R6.1@14.82,43.815 ; R50.1@20.32,74.676 21.209,74.676 21.59,74.295 v1(21.59,73.914) ; SW1.9@20.32,86.995 18.923,88.392 14.097,88.392 SW1.12@12.7,86.995 12.7,83.693 8.763,79.756 8.763,73.533 ; v1(23.749,61.722) 23.622,61.595 23.622,58.42 ; v1(24.384,19.558) 24.511,19.431 24.511,17.272 ; R16.1@24.511,13.716 24.511,17.272 ; v1(25.4,61.722) 27.051,61.722 27.432,62.103 27.94,62.103 28.36,61.683 R3.1@28.36,60.96 ; R34.1@28.067,31.027 28.103,30.991 28.103,30.234 28.704,29.632 28.704,25.017 v1(28.956,24.765) ; R15.1@28.194,13.716 28.194,14.732 27.813,15.113 27.813,16.764 27.305,17.272 24.511,17.272 ; C15.1@35.687,51.435 33.02,51.435 33.02,52.451 32.258,53.213 30.734,53.213 ; v1(37.719,41.529) 37.885,41.363 R33.1@39.751,41.363 ; R22.1@38.1,44.704 v1(36.576,44.704) 31.75,44.704 30.734,45.72 30.734,53.213 ; 8.763,73.533 12.7,73.533 ; 8.763,73.533 5.842,70.612 5.842,58.674 7.747,56.769 7.747,54.483 8.255,53.975 C4.1@13.78,53.975 13.843,54.038 13.843,57.023 15.24,58.42 ; 10.287,16.891 12.827,16.891 13.335,16.383 13.335,15.621 18.669,15.621 18.796,15.748 20.955,15.748 20.828,15.875 20.828,16.764 21.336,17.272 24.511,17.272 ; 11.303,50.165 v1(11.303,43.815) 11.557,43.815 12.954,42.418 14.351,42.418 14.82,42.887 R6.1@14.82,43.815 ; 15.24,58.42 23.622,58.42 ; 23.622,58.42 23.622,56.515 25.4,54.737 25.4,53.721 25.908,53.213 30.734,53.213
  Bottom Layer w0.254: v1(45.593,20.32) v1(45.593,23.114)
  Bottom Layer w0.508: v1(11.303,38.989) v1(11.303,43.815) ; v1(15.113,73.533) 15.748,74.168 21.336,74.168 v1(21.59,73.914) ; v1(23.749,61.722) v1(25.4,61.722) ; v1(24.384,19.558) 24.384,20.193 v1(28.956,24.765) ; v1(36.576,44.704) 36.576,42.672 v1(37.719,41.529)
BLACK: K1.13 U4.18 | length 24.8
  Top Layer w0.254: U4.18@53.075,36.572 53.075,37.835 53.467,38.227 v1(53.848,38.608)
  Top Layer w0.508: U4.18@53.086,36.576 53.086,37.71 53.467,38.091 53.467,38.227
  Top Layer w0.762: 53.52,38.324 53.848,38.652 v1(53.848,39.497)
  Bottom Layer w0.762: K1.13@49.022,23.114 50.673,23.114 51.181,23.622 51.181,26.289 52.705,27.813 52.705,34.671 53.848,35.814 v1(53.848,38.608) v1(53.848,39.497)
BLACK_M1: J6.1 K1.11 | length 20
  Bottom Layer w0.762: J6.1@45.974,7.62 45.974,9.525 47.498,11.049 49.403,11.049 51.562,13.208 51.562,20.574 K1.11@54.102,23.114
BLACK_M2: J7.1 K1.9 | length 19.6
  Top Layer w0.762: K1.9@59.182,23.114 59.182,20.955 57.277,19.05 57.277,14.478 60.071,11.684 61.849,11.684 62.865,10.668 J7.1@62.865,7.62
BLUE: J6.2 J7.2 U4.25 | length 67.3
  Top Layer w0.254: v1(47.625,38.1) 47.738,38.1 47.745,38.1 48.002,37.842 48.514,37.331 48.525,37.32 U4.25@48.525,36.572
  Top Layer w0.508: 48.002,37.842 48.182,37.842 48.514,37.51 48.514,37.331 U4.25@48.514,36.576
  Top Layer w0.762: v1@47.615,38.989 47.615,38.11 v1(47.625,38.1) ; v1@47.738,38.1 v1@47.915,37.923
  Bottom Layer w0.762: v1(47.625,38.989) v1(47.625,38.1) 48.399,37.326 48.399,30.667 47.582,29.85 47.582,28.913 45.284,26.615 45.284,24.079 44.692,23.487 44.692,19.935 44.704,19.923 44.704,12.192 43.688,11.176 43.688,6.223 44.831,5.08 49.53,5.08 ; 49.558,5.08 65.024,5.08 66.294,6.35 J7.2@66.294,7.747 ; 49.558,5.108 J6.2@49.558,7.645
DIR_A3979: R12.1 U2.25 | length 17.8
  Top Layer w0.254: U2.25@16.174,39.751 16.174,38.309 19.982,34.501 23.03,34.501 23.634,33.897 24.88,33.897 v1(24.765,33.782) ; v1(27.178,36.195) R12.1@29.376,36.195 R12.1@29.464,36.195
  Bottom Layer w0.254: v1(24.765,33.782) v1(27.178,36.195)
FLOW_METER: R19.1 U2.22 | length 27.1
  Top Layer w0.254: U2.22@18.124,39.751 18.124,38.518 20.84,35.802 24.431,35.802 26.246,33.987 26.246,27.694 26.84,27.1 26.84,22.014 25.908,21.082 R19.1@25.908,18.796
